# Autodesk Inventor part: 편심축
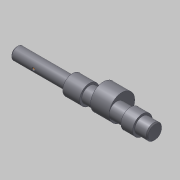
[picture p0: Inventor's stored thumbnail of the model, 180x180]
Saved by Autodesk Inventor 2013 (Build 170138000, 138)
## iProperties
Company: 한국ATC센터
Created: 2015-12
Part Number: 편심축
Document SubType Name: Modeling
Designer: mdu
Density: 7.86 g/cm^3
Mass: 225.444 g
Surface Area: 81.7069 cm^2
Volume: 28.6825 cm^3
Material: 강철, 연강
Author: mdu
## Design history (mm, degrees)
sketch "스케치1"
  geometry: L1 (-86, 0)-(86, 0); L2 (-86, 0)-(-86, 6); L3 (-86, 6)-(-32, 6); L4 (-32, 6)-(-32, 9.5); L5 (-32, 9.5)-(-15.5, 9.5); L6 (-15.5, 9.5)-(-15.5, 7.5); L7 (-15.5, 7.5)-(48, 7.5); L8 (86, 6)-(86, 0); L9 (36, 7.5)-(36, 9.5); L10 (36, 9.5)-(24.5, 9.5); L11 (24.5, 9.5)-(24.5, 7.5); L12 (48, 7.5)-(48, 6); L13 (48, 6)-(86, 6); 2 further points
  constraints: 26 end point, 6 parallel, 6 perpendicular, 2 point on line, 1 coincident, 1 horizontal, 1 midpoint
  dimensions: "d1" = 12 diameter of L3 L1; "d2" = 15 diameter of L7 L1; "d4" = 16.5 distance of L4.end L5.end; "d5" = 19 diameter of L5 L1; "d24" = 11.5 distance of L9.end L10.end; "d25" = 19 diameter of L10 L1; "d27" = 40 distance between parallel lines of L11 L6; "d28" = 54 distance of L2.end L3.end; "d29" = 50 distance between parallel lines of L8 L9; "d41" = 38 distance between parallel lines of L8 L12; "d42" = 12 diameter of L13 L1
revolve "회전1" stored, may be unused: angle "d6" = 90 deg
node "작업 평면1"
sketch "스케치2"
  geometry: C1 r 7.5 at (0, 0) reference; C2 r 12.5 at (0, 5); 1 further point
  constraints: 1 centre point, 1 tangent, 1 vertical alignment
  dimensions: "d9" = 25 diameter of C2
extrude "돌출1" join sketch "스케치2" distance "d10" = 18; taper "d11" = 0 deg
chamfer "모따기1" distance "d12" = 1; stored, may be unused: second distance "d13" = 2, angle "d14" = 45 deg
node "작업 평면2"
sketch "스케치3"
  geometry: L1 (7, -2)-(21, -2); L2 (21, 2)-(7, 2); L3 (27, 5)-(27, -5) reference; A1 r 2 centre (21, 0) between (21, -2) and (21, 2); A2 r 2 centre (7, 0) between (7, 2) and (7, -2); 2 further points
  constraints: 4 end point, 4 point on circle, 4 tangent, 2 centre point, 1 horizontal, 1 horizontal alignment, 1 midpoint, 1 parallel
  dimensions: "d18" = 4 distance edge to line of A1 L3; "d19" = 4 distance between parallel lines of L2 L1; "d20" = 18 dimension on A1 A2
extrude "돌출2" cut sketch "스케치3" distance "d21" = 2.5; taper "d22" = 0 deg
revolve "회전2" stored, may be unused: angle "d26" = 90 deg
node "작업 평면3"
sketch "스케치4"
  geometry: L1 (44, 5)-(44, -5) reference; 2 further points
  constraints: 1 horizontal alignment
  dimensions: "d30" = 12 distance from line of point (32, 0) L1
hole "구멍1" sketch "스케치4" at (32, 0) diameter "d31" = 6; stored, may be unused: countersink angle "d35" = 90 deg, drill point angle "d37" = 118 deg; dims "d32" = 6, "d33" = 14, "d34" = 3, "d36" = 8
node "작업 평면4"
sketch "스케치5"
  geometry: C1 r 3 at (32, 0) reference; C2 r 8 at (32, 0); 2 further points
  constraints: 1 centre point, 1 coincident, 1 other
  dimensions: "d38" = 16 diameter of C2
extrude "돌출3" cut sketch "스케치5" distance "d39" = 3; taper "d40" = 0 deg
sketch "스케치6"
  geometry: L1 (-85, -6)-(-32, -6) reference; L2 (-86, -5)-(-86, 5) reference; L3 (-85, 6)-(-32, 6) reference; L4 (-64, 6)-(-64, -6); L5 (-64, -6)-(-62.5, -6); L6 (-64, -4.5)-(-62.5, -6); L7 (-64, -6)-(-64, -4.5); 2 further points
  constraints: 8 end point, 4 point on line, 2 perpendicular, 1 coincident
  dimensions: "d43" = 22 distance between parallel lines of L4 L2; "d44" = 45 deg angle of L6 L7; "d45" = 3 diameter of L5.end L4
revolve "회전3" stored, may be unused: angle "d46" = 90 deg
node "작업점1"
chamfer "모따기3" distance "d47" = 0.5; stored, may be unused: second distance "d48" = 2, angle "d49" = 45 deg
sketch "스케치7"
  geometry: C1 r 7.5 at (0, 0) reference; 1 further point
extrude "돌출4" cut sketch "스케치7" stored distance "d50" = 10; taper "d51" = 0 deg
chamfer "모따기4" distance "d52" = 1; stored, may be unused: second distance "d53" = 2, angle "d54" = 45 deg
node "작업 평면6"
node "솔리드1"
node "투영된 루프1"
other parameters: "d7" = 8.5
